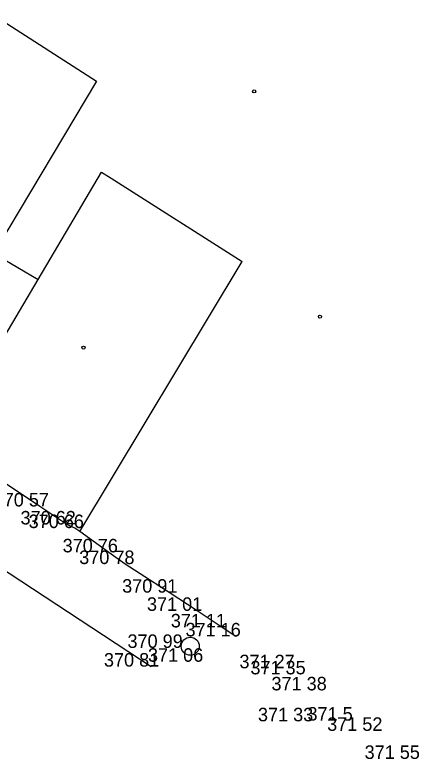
# Model space of a CAD drawing. Extents: x -688316 to -688024, y -973785 to -973591.
# Drawn here: x -688069.85 to -688047.4, y -973718.17 to -973676.81 of the extents above; entities that cross this region are included whole.
import ezdxf

# ---------------------------------------------------------------- set-up
doc = ezdxf.new("R2010")
doc.units = 0
for name, color, linetype in [('Vrstva 10', 7, 'Continuous'), ('Vrstva 27', 7, 'Continuous'), ('Vrstva 3', 7, 'Continuous'), ('Vrstva 5', 7, 'Continuous'), ('Vrstva 58', 7, 'Continuous'), ('Vrstva 6', 7, 'Continuous')]:
    doc.layers.add(name, color=color, linetype=linetype)

# ---------------------------------------------------------------- blocks, each defined once
blk = doc.blocks.new('B_NESP')
at = {"layer": 'Vrstva 58'}
blk.add_circle((0, 0), 0.875, dxfattribs=at)
blk = doc.blocks.new('SAK')
at = {"layer": 'Vrstva 27'}
blk.add_circle((0, 0), 5, dxfattribs=at)

msp = doc.modelspace()

# ---------------------------------------------------------------- linework, layer by layer
at = {"layer": 'Vrstva 10'}
msp.add_line((-688072.24, -973706.48), (-688062.29, -973713.03), dxfattribs=at)
at = {"layer": 'Vrstva 5'}
for p, q in [((-688071.06, -973676.81), (-688065.32, -973680.49)), ((-688065.32, -973680.49), (-688071.03, -973690.06)), ((-688068.56, -973691.52), (-688065.04, -973685.56)), ((-688065.04, -973685.56), (-688064.5, -973685.88)), ((-688064.5, -973685.88), (-688057.23, -973690.52)), ((-688071.03, -973690.06), (-688068.56, -973691.52)), ((-688066.24, -973705.53), (-688057.23, -973690.52)), ((-688073.89, -973700.55), (-688068.56, -973691.52)), ((-688068.47, -973704.13), (-688071.92, -973701.82)), ((-688066.52, -973705.33), (-688066.97, -973705.13)), ((-688061.28, -973708.92), (-688063.72, -973707.33)), ((-688058.34, -973710.85), (-688059.72, -973709.93))]:
    msp.add_line(p, q, dxfattribs=at)
msp.add_lwpolyline([(-688064.64, -973706.68), (-688066.24, -973705.53), (-688066.52, -973705.33)], dxfattribs=at)
at = {"layer": 'Vrstva 6'}
for p, q in [((-688066.97, -973705.13), (-688068.47, -973704.13)), ((-688063.72, -973707.33), (-688064.64, -973706.68)), ((-688059.72, -973709.93), (-688061.28, -973708.92)), ((-688057.58, -973711.35), (-688058.34, -973710.85))]:
    msp.add_line(p, q, dxfattribs=at)

# ---------------------------------------------------------------- block references
at = {"layer": 'Vrstva 27', "xscale": 0.1, "yscale": 0.10000000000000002}
msp.add_blockref('SAK', (-688060.11, -973711.9), dxfattribs=at)
at = {"layer": 'Vrstva 58', "xscale": 0.1, "yscale": 0.10000000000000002}
for p in [(-688056.56, -973681.06), (-688056.56, -973681.06), (-688056.56, -973681.06), (-688056.56, -973681.06), (-688052.91, -973693.58), (-688052.91, -973693.58), (-688052.91, -973693.58), (-688052.91, -973693.58), (-688066.04, -973695.3), (-688066.04, -973695.3), (-688066.04, -973695.3), (-688066.04, -973695.3)]:
    msp.add_blockref('B_NESP', p, dxfattribs=at)

# ---------------------------------------------------------------- texts
at = {"layer": 'Vrstva 3'}
for s, p in [('370 57 ', (-688071.027, -973704.13)), ('370 57 ', (-688071.027, -973704.13)), ('370 57 ', (-688071.027, -973704.13)), ('370 57 ', (-688071.027, -973704.13)), ('370 57 ', (-688071.027, -973704.13)), ('370 57 ', (-688071.027, -973704.13)), ('370 57 ', (-688071.027, -973704.13)), ('370 62 ', (-688069.536, -973705.13)), ('370 62 ', (-688069.536, -973705.13)), ('370 62 ', (-688069.536, -973705.13)), ('370 62 ', (-688069.536, -973705.13)), ('370 62 ', (-688069.536, -973705.13)), ('370 62 ', (-688069.536, -973705.13)), ('370 62 ', (-688069.536, -973705.13)), ('370 66 ', (-688069.086, -973705.33)), ('370 66 ', (-688069.086, -973705.33)), ('370 66 ', (-688069.086, -973705.33)), ('370 66 ', (-688069.086, -973705.33)), ('370 66 ', (-688069.086, -973705.33)), ('370 66 ', (-688069.086, -973705.33)), ('370 66 ', (-688069.086, -973705.33)), ('370 76 ', (-688067.197, -973706.68)), ('370 76 ', (-688067.197, -973706.68)), ('370 76 ', (-688067.197, -973706.68)), ('370 76 ', (-688067.197, -973706.68)), ('370 76 ', (-688067.197, -973706.68)), ('370 76 ', (-688067.197, -973706.68)), ('370 76 ', (-688067.197, -973706.68)), ('370 78 ', (-688066.277, -973707.33)), ('370 78 ', (-688066.277, -973707.33)), ('370 78 ', (-688066.277, -973707.33)), ('370 78 ', (-688066.277, -973707.33)), ('370 78 ', (-688066.277, -973707.33)), ('370 78 ', (-688066.277, -973707.33)), ('370 78 ', (-688066.277, -973707.33)), ('370 91 ', (-688063.893, -973708.92)), ('370 91 ', (-688063.893, -973708.92)), ('370 91 ', (-688063.893, -973708.92)), ('370 91 ', (-688063.893, -973708.92)), ('370 91 ', (-688063.893, -973708.92)), ('370 91 ', (-688063.893, -973708.92)), ('370 91 ', (-688063.893, -973708.92)), ('371 01 ', (-688062.515, -973709.93)), ('371 01 ', (-688062.515, -973709.93)), ('371 01 ', (-688062.515, -973709.93)), ('371 01 ', (-688062.515, -973709.93)), ('371 01 ', (-688062.515, -973709.93)), ('371 01 ', (-688062.515, -973709.93)), ('371 01 ', (-688062.515, -973709.93)), ('371 11 ', (-688061.191, -973710.85)), ('371 11 ', (-688061.191, -973710.85)), ('371 11 ', (-688061.191, -973710.85)), ('371 11 ', (-688061.191, -973710.85)), ('371 11 ', (-688061.191, -973710.85)), ('371 11 ', (-688061.191, -973710.85)), ('371 11 ', (-688061.191, -973710.85)), ('371 16 ', (-688060.375, -973711.35)), ('371 16 ', (-688060.375, -973711.35)), ('371 16 ', (-688060.375, -973711.35)), ('371 16 ', (-688060.375, -973711.35)), ('371 16 ', (-688060.375, -973711.35)), ('371 16 ', (-688060.375, -973711.35)), ('371 16 ', (-688060.375, -973711.35)), ('370 99 ', (-688063.597, -973711.99)), ('370 99 ', (-688063.597, -973711.99)), ('370 99 ', (-688063.597, -973711.99)), ('370 99 ', (-688063.597, -973711.99)), ('370 99 ', (-688063.597, -973711.99)), ('370 99 ', (-688063.597, -973711.99)), ('370 99 ', (-688063.597, -973711.99)), ('370 81 ', (-688064.903, -973713.03)), ('370 81 ', (-688064.903, -973713.03)), ('370 81 ', (-688064.903, -973713.03)), ('370 81 ', (-688064.903, -973713.03)), ('370 81 ', (-688064.903, -973713.03)), ('370 81 ', (-688064.903, -973713.03)), ('370 81 ', (-688064.903, -973713.03)), ('371 06 ', (-688062.459, -973712.76)), ('371 06 ', (-688062.459, -973712.76)), ('371 06 ', (-688062.459, -973712.76)), ('371 06 ', (-688062.459, -973712.76)), ('371 06 ', (-688062.459, -973712.76)), ('371 06 ', (-688062.459, -973712.76)), ('371 06 ', (-688062.459, -973712.76)), ('371 27 ', (-688057.379, -973713.12)), ('371 27 ', (-688057.379, -973713.12)), ('371 27 ', (-688057.379, -973713.12)), ('371 27 ', (-688057.379, -973713.12)), ('371 27 ', (-688057.379, -973713.12)), ('371 27 ', (-688057.379, -973713.12)), ('371 27 ', (-688057.379, -973713.12)), ('371 35 ', (-688056.771, -973713.46)), ('371 35 ', (-688056.771, -973713.46)), ('371 35 ', (-688056.771, -973713.46)), ('371 35 ', (-688056.771, -973713.46)), ('371 35 ', (-688056.771, -973713.46)), ('371 35 ', (-688056.771, -973713.46)), ('371 35 ', (-688056.771, -973713.46)), ('371 38 ', (-688055.601, -973714.35)), ('371 38 ', (-688055.601, -973714.35)), ('371 38 ', (-688055.601, -973714.35)), ('371 38 ', (-688055.601, -973714.35)), ('371 38 ', (-688055.601, -973714.35)), ('371 38 ', (-688055.601, -973714.35)), ('371 38 ', (-688055.601, -973714.35)), ('371 33 ', (-688056.351, -973716.07)), ('371 33 ', (-688056.351, -973716.07)), ('371 33 ', (-688056.351, -973716.07)), ('371 33 ', (-688056.351, -973716.07)), ('371 33 ', (-688056.351, -973716.07)), ('371 33 ', (-688056.351, -973716.07)), ('371 33 ', (-688056.351, -973716.07)), ('371 5  ', (-688053.601, -973716.03)), ('371 5  ', (-688053.601, -973716.03)), ('371 5  ', (-688053.601, -973716.03)), ('371 5  ', (-688053.601, -973716.03)), ('371 5  ', (-688053.601, -973716.03)), ('371 5  ', (-688053.601, -973716.03)), ('371 5  ', (-688053.601, -973716.03)), ('371 52 ', (-688052.509, -973716.6)), ('371 52 ', (-688052.509, -973716.6)), ('371 52 ', (-688052.509, -973716.6)), ('371 52 ', (-688052.509, -973716.6)), ('371 52 ', (-688052.509, -973716.6)), ('371 52 ', (-688052.509, -973716.6)), ('371 52 ', (-688052.509, -973716.6)), ('371 55 ', (-688050.429, -973718.16)), ('371 55 ', (-688050.429, -973718.16)), ('371 55 ', (-688050.429, -973718.16)), ('371 55 ', (-688050.429, -973718.16)), ('371 55 ', (-688050.429, -973718.16)), ('371 55 ', (-688050.429, -973718.16)), ('371 55 ', (-688050.429, -973718.16))]:
    msp.add_text(s, height=0.75, dxfattribs=at).set_placement(p)

doc.saveas('drawing.dxf')
